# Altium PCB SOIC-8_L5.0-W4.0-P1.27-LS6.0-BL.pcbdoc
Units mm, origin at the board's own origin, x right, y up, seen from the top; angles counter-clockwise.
Board outline 17.7 x 20.06 mm, 2 copper layers (Top Layer, Bottom Layer), stack 0 mm thick; 1 components, 0 nets, 8 pads, 0 vias.
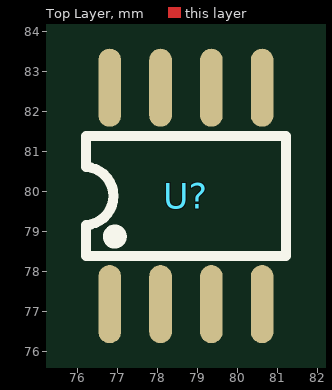
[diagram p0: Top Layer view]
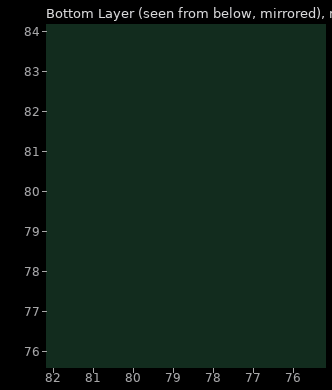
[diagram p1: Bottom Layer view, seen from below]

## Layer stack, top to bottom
Top Layer: signal copper (thickness not stored)
Bottom Layer: signal copper (thickness not stored)

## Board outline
87.55,69.85 69.85,69.85 69.85,89.91 87.55,89.91

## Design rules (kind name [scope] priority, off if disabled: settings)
PasteMaskExpansion "Paste Mask Expansion" [All] p1: expansion=0
SolderMaskExpansion "Solder Mask Expansion" [IsVia] p1: expansion=-25.4 istentingtop=TRUE
SolderMaskExpansion "Solder Mask Expansion" [All] p2: expansion=0.051 istentingtop=FALSE

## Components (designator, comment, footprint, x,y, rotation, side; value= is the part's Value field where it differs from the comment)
U? "" SOIC-8_L5.0-W4.0-P1.27-LS6.0-BL 78.7,79.88 r0 top

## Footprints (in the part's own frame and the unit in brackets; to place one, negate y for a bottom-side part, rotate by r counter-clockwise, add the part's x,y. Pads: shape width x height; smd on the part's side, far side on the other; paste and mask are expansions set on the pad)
SOIC-8_L5.0-W4.0-P1.27-LS6.0-BL [mil]
  oval 22.38x76.78 smd: 1(-75,-106.5) 2(-25,-106.5) 3(25,-106.5) 4(75,-106.5) 5(75,106.5) 6(25,106.5) 7(-25,106.5) 8(-75,106.5)
  silkscreen extent -98,-59 98,59

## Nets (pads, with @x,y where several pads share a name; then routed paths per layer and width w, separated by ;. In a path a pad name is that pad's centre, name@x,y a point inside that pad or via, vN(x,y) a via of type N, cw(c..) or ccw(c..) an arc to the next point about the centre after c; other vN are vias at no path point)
pads on no net: U?.1 U?.2 U?.3 U?.4 U?.5 U?.6 U?.7 U?.8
